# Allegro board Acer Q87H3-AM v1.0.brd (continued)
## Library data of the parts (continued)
C1-C4 C7-C9 C47-C95 C98-C105 C107-C115 C117-C123 C125-C134 C136 C138-C143 C146-C148 C151-C153 C155-C157 C160 C162-C167 C169-C211 C213 C215 C217 C219 C221 C223-C227 C229-C236 C239 C242 C245-C247 C249-C252 C254 C256 C262 C264 C281 C282 C284 C285 C287 C289-C310 C326 C329 C330 C333 C334 C337-C339 C342-C362 C364-C369 C371 C373-C379 C383-C385 C387 C388 C391-C396 C398-C406 C408-C415 C418-C420 C422 C423 C426 C428 C429 C431-C441 C444-C446 C448-C450 C452 C453 C455-C458 C460 C461 C463-C483 C486-C494 C496-C504 C506 C509 C510 C522-C526 C528 C531-C538 C541 C544 C550 C553 C554 C557-C559 C563 C571 C574 C576 C580 C583 C584 C591 C592 C597 C598 C602 C606 C607 C613 C624 C625 C652-C654 C659 C660 C663 C664 C666 C668 C670 C675 C677-C681 C683-C686 C689-C691 C696-C704 C706-C711 C722-C728 C736 C737 C740 C741 C745-C749 C751-C757 C760 C762 C763 C765-C767 C772-C775 C787-C793 C797 C800-C804 C807-C810 C815-C821 C823 C824 C827-C836 C839-C842 C844-C846 C848-C851 C854 C856-C858 SC1-SC12 SC15-SC20 SC22 SC25 SC27 SC30 SC31 SC34-SC41 SC43-SC46 SC48-SC52 = C0402_1
C6 C116 C144 C145 C149 C150 C154 C158 C168 C228 C237 C238 C240 C248 C253 C257-C261 C263 C268-C271 C273 C279 C280 C283 C286 C325 C328 C332 C336 C341 C380 C381 C386 C389 C390 C417 C442 C484 C495 C513 C517 C540 C548 C549 C551 C552 C564 C573 C578 C579 C590 C594 C600 C604 C605 C608 C610 C611 C676 C682 C705 C729-C731 C735 C738 C739 C742 C750 C761 C764 C768 C771 C776-C779 C781-C784 C794 C795 C825 C826 C838 C855 SC21 SC23 SC24 SC26 SC28 SC29 SC32 SC33 = C0603_1
C10-C12 C15-C46 C135 C137 C159 C161 C241 C243 C244 C255 C278 C324 C327 C331 C335 C340 C370 C372 C382 C397 C407 C425 C427 C443 C447 C451 C459 C462 C505 C507 C508 C511 C512 C514-C516 C518-C521 C527 C542 C543 C545-C547 C555 C556 C572 C575 C577 C581 C582 C585-C589 C593 C595 C596 C599 C601 C603 C609 C612 C669 C671-C674 C732-C734 C743 C744 C758 C759 C769 C770 C780 C785 C786 C796 C798 C799 C805 C806 C811-C814 C822 C843 SC14 = C0805_1
CMK1-CMK4 CMK33-CMK36 = WCM2012F2S_1
CMK9-CMK32 = CMM21_1
CMK37 = CMM21_R0402
CN1-CN8 = 8P4C
CODEC = LQFP48
COM1 = D-SUB_9P-KORTAK_1
COM2 = J5X2_COM
CPU1 = LGA1150_HSW_SKT-INTEL_1
CPU_FAN SYS_FAN = FAN4X1
D1 D8 D18 D20 D21 D23 SD1 = BAT54_132_2
D2 D3 D16 D17 = FPC_4P10_R_1
D5-D7 D11 = 1N4148
D9 D34 D40 = BAV99_132_2
D14 D15 D29-D32 = SOD_123_2
D19 D35-D39 = SOD_523
D22 = SOT23_RAC_Z_2
D24 D25 D27 D28 SD2 = SOT23_3L
DIMM1-DIMM4 = DDR3_240P_2
DP1 DP2 = CONN_DISPLAYPORT_19P_1
DVI-D = DVI_29P_MB_2
EC1 EC3 = EC3D5_8_H11MM_1P
EC2 EC4 EC6 EC46-EC48 = EC3D5_8_H11D5MM_1P
EC5 EC7-EC19 EC25 EC28-EC30 EC45 EC60 = EC2D5_6D3_H11MM
EC20-EC24 EC27 EC42 EC49-EC55 EC57 EC59 = EC2D5_6D3_H8MM
EC56 EC58 EC61 = EC3D5_8_H12MM_1P
F1 = FUSE_SMD_1
F5 = F1812
F_AUDIO = J5X2_AUDIO_1
F_PANEL = J7X2_PANEL_10P
F_USB1 F_USB2 = J5X2_USB_1394
F_USB3 = J5X1_CR
FB1-FB10 FB13-FB17 PFB1 PFB4-PFB8 PFB10 PFB11 R366 SFB1 SFB2 = FB0603_1
H1-H8 = HOLE8_5
ILAN = QFN48_PT04_3X3
INT_SPK = J4X2_4P
L1 = CHOKE_4R7K_PT3D35MM_SMD
L2 = CHOKE_2R2N_SMD_2P
L3 L7 L12 = CHOKE_9D5X11_PT7MM_H_2
L4 = CHOKE_1R0M-R_1
L5 PFB2 PFB9 PFB12 PFB13 = FB0805_1
L6 = CHOKE_4R7_PT2D65MM_SMD
L8-L11 = CHOKE-R36M_PT6D6X4D2MM_R
L13 L14 = CHOKE_2R0M_PT8X6D8MM
LPT = J13X2_LPT_1
ME_TEST = J3X2
MN1 MN2 QN1 QN6-QN13 QN20-QN23 QN30 QN34 QN36 QN38 QN44 QN47 QN55 QN56 QN58 QN68 QN69 QN71-QN76 QN82 QP9 QSW1-QSW4 = SOT23_GDS_2
P1-P12 R623 R631 R937 R941 = SHORT2-NMNP
PCH1 = BGA708_LYNX-INTEL
PCI = PCI_120P-AB
PCIE1X = PCIE_X1_36P_2
PCIE16X_1 PCIE16X_2 = PCIE_X16_164P_4
PSKM = KB_MS
Q1-Q6 = SOT363_6P
Q7 ROM1 U22 U31 U32 = SOP8_W150_PT50
QCH1-QCH4 QCL1-QCL8 QD3H1 QD3L1 QD3L2 QD5H1 QD5H2 QD5L1 QD5L2 QMH1 QML1 QML2 = Q_TDSON8-GDS-4
QN2-QN5 QN24-QN29 QN31-QN33 QN35 QN37 QN39-QN43 QN45 QN46 QN48 QN49 QN51 QN53 QN54 QN57 QN59-QN67 QN77-QN81 QN83 QN84 QP3-QP8 SQP1 = SOT23_BCE_2
QN50 QN52 = TO252_GDS
QP2 = TO251_BCE_PT90_1
R1 R4-R13 R15-R53 R56-R68 R71-R73 R75-R79 R81-R83 R85-R89 R95 R96 R98 R103-R127 R129-R133 R136-R161 R163-R229 R231-R248 R250-R256 R258 R259 R261-R265 R267-R271 R275 R277-R314 R316-R326 R329-R345 R349-R360 R367-R374 R376-R390 R395-R398 R400 R402 R403 R405 R408-R438 R440 R442-R449 R451-R454 R456-R461 R468 R471-R477 R479-R505 R507 R509-R511 R513-R515 R517-R520 R523-R526 R528-R531 R551 R552 R554 R555 R558 R561 R562 R566 R568 R570 R571 R574 R576-R580 R582-R586 R588-R591 R593 R595 R596 R598 R600-R602 R604 R606-R609 R611-R622 R624-R630 R633 R636-R638 R641-R654 R657 R694 R695 R737-R741 R761-R773 R777 R778 R783 R784 R786 R787 R789-R791 R793-R805 R808 R810 R814-R816 R818-R821 R823 R824 R826-R828 R830-R833 R835 R837-R840 R843 R845-R859 R861-R868 R871-R881 R885-R887 R889-R892 R894-R906 R909 R911 R912 R914-R919 R921 R923 R924 R927-R936 R938 R939 R942-R945 R949-R978 R980-R991 R994-R1001 RT1-RT3 SR2 SR3 SR5-SR14 SR16-SR24 SR30 SR32-SR34 SR36-SR38 SR40 SR45 SR46 SR48 SR49 SR51 SR52 SR54-SR59 = R0402_1
R80 R84 R128 R266 R375 R441 R450 R516 R564 R565 R567 R569 R572 R573 R597 R599 R610 R634 R635 R639 R640 R813 R822 R829 R836 R842 R844 R860 R869 R870 R883 R884 R888 R893 R908 R910 R913 R922 R925 R926 SR53 = R0805_1
R162 R249 R257 R260 R391-R394 R401 R404 R406 R407 R462-R467 R563 R592 R603 R632 R760 R809 R811 R812 R817 R825 R834 R841 R882 R907 R920 R1002 SR1 SR43 SR44 SR50 = R0603_1
R276 R347 R365 R469 R470 = R0603-SHORT_1
R455 = R0805-SHORT-NMNP
R508 R512 SR15 = R0603-SHORT_1-NMNP
R575 = R2512_1
RJ1-RJ12 RJ17 = RJ3_0402
RLAN = QFN64_RTL8111DP_1
RN1 RN2 RN7 RN8 RN19-RN25 RN38-RN40 RN43 RN44 = 8P4R
RN9-RN15 RN26-RN35 RN45 RN46 = 8P4R-0402
ROM2 SPIROM1 SPIROM2 = SOP8_W210_PT50
SATA1-SATA5 = SATA3_7P-HI-TOP
SATA_PWR1 SATA_PWR2 = CON6X1_2D5MM-PINREX
SJ1 = 2X30_XDP_CONN-NMNP
SPI_DEBUG = J6X2_PT1D27MM_SMD_2P
STP1-STP19 TP12 TP14 TP15 TP21 TP23 TP_VGA = TP30_SMD
SU1 SU2 U3 U6 U7 U9 U14 U15 U17 U18 U20 U24 U26 U28 = SOT23_6P_2
THER_HD = J3X2_SPDIF
TPM = J10X2_TPM_4P-ACER
U1 U2 U4 U5 U8 U10 = SOT1059_10P_1
U11 = LQFP128_PT04
U12 U13 U16 U25 = SOT23_8P_1
U19 U29 = PSOP8_W150_PT50_PAD-UP7719B_1
U21 = QFP128
U23 = TSSOP28_W170_PT065
U30 = SOP8_W150_PT50-104X120
U33 = DFN10_RT8106A_1
U34 = PSOP8_W150_PT50_PAD-UP6281
U35 U36 = SOT23_5P_1
U39 = QFN40_PT04_E2201
U40 = DFN8_PT05_ISL6208_1
U41 = QFN28_SM331L_PT04MM_1
U42 U43 = TSSOP20_W170_PT065
USB2X4 = USBX4_2
USB3_LAN = RJ45_USB3_32P
USB3F1 = CON10X2_2MM_20P_USB3_1
VGA = DVI_D-SUB_15F_1
X1-X3 = CRYSTAL
Y1 = ETXTALS-SPAD

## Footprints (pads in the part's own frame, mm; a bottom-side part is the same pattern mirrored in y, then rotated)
1N4148
  rect 1.524x1.778 smd: N(1.727,0) P(-1.727,0)
2X30_XDP_CONN-NMNP
  round 1.295 hole 1.295 unplated: (-10.071,2.667) (10.071,2.667)
  rect 0.203x2.54 smd: 1(-7.254,-3.231) 2(-7.254,2.865) 3(-6.754,-3.231) 4(-6.754,2.865) 5(-6.253,-3.231) 6(-6.253,2.865) 7(-5.753,-3.231) 8(-5.753,2.865) 9(-5.253,-3.231) 10(-5.253,2.865) 11(-4.752,-3.231) 12(-4.752,2.865) 13(-4.252,-3.231) 14(-4.252,2.865) 15(-3.752,-3.231) 16(-3.752,2.865) 17(-3.251,-3.231) 18(-3.251,2.865) 19(-2.751,-3.231) 20(-2.751,2.865) 21(-2.25,-3.231) 22(-2.25,2.865) 23(-1.75,-3.231) 24(-1.75,2.865) 25(-1.25,-3.231) 26(-1.25,2.865) 27(-0.749,-3.231) 28(-0.749,2.865) 29(-0.249,-3.231) 30(-0.249,2.865) 31(0.251,-3.231) 32(0.251,2.865) 33(0.752,-3.231) 34(0.752,2.865) 35(1.252,-3.231) 36(1.252,2.865) 37(1.753,-3.231) 38(1.753,2.865) 39(2.253,-3.231) 40(2.253,2.865) 41(2.753,-3.231) 42(2.753,2.865) 43(3.254,-3.231) 44(3.254,2.865) 45(3.754,-3.231) 46(3.754,2.865) 47(4.255,-3.231) 48(4.255,2.865) 49(4.755,-3.231) 50(4.755,2.865) 51(5.255,-3.231) 52(5.255,2.865) 53(5.756,-3.231) 54(5.756,2.865) 55(6.256,-3.231) 56(6.256,2.865) 57(6.756,-3.231) 58(6.756,2.865) 59(7.257,-3.231) 60(7.257,2.865)
8P4C
  rect 0.61x1.143 smd: 1(-1.219,-0.826) 2(-1.219,0.826) 7(1.219,-0.826) 8(1.219,0.826)
  rect 0.508x1.143 smd: 3(-0.406,-0.826) 4(-0.406,0.826) 5(0.406,-0.826) 6(0.406,0.826)
8P4R
  rect 0.61x1.143 smd: 1(-1.219,-0.826) 2(-1.219,0.826) 7(1.219,-0.826) 8(1.219,0.826)
  rect 0.508x1.143 smd: 3(-0.406,-0.826) 4(-0.406,0.826) 5(0.406,-0.826) 6(0.406,0.826)
8P4R-0402
  rect 0.432x0.864 smd: 1(-0.826,-0.638) 2(-0.826,0.638) 7(0.826,-0.638) 8(0.826,0.638)
  rect 0.279x0.864 smd: 3(-0.25,-0.638) 4(-0.25,0.638) 5(0.25,-0.638) 6(0.25,0.638)
ATX_PWR_4P_1
  rect 2.286x2.286 hole 1.422: 1(-2.1,2.8)
  round 2.286 hole 1.422: 2(2.1,2.8) 3(-2.1,-2.8) 4(2.1,-2.8)
ATX_PWR_12P-RUIYE
  rect 1.905x1.905 hole 1.397: 1(-10.5,2.75)
  round 1.905 hole 1.397: 2(-6.3,2.75) 3(-2.1,2.75) 4(2.1,2.75) 5(6.3,2.75) 6(10.5,2.75) 7(-10.5,-2.75) 8(-6.3,-2.75) 9(-2.1,-2.75) 10(2.1,-2.75) 11(6.3,-2.75) 12(10.5,-2.75)
AUDIO_JACK_13P-KORTAK
  round 2.337 hole 2.337 unplated: (0,4.85)
  round 1.372 hole 1.016: 1P(2.5,0.95) 1Q(-2.5,0.95) 2P(1.25,-4.05) 2Q(-1.25,-4.05) 3P(1.25,-9.05) 3Q(-1.25,-9.05) 5(0,0.95) 11(-5,0.95) 14(5,0.95) 21(-3.75,-4.05) 24(3.75,-4.05) 31(-3.75,-9.05) 34(3.75,-9.05)
  round 2.692 hole 2.337: G1(-6.05,4.85) G2(6.05,4.85) G3(-6.05,-6.45) G4(6.05,-6.45)
BAT54_132_2
  rect 1.016x1.016 smd: 1(-1.016,-1.143) 2(1.016,-1.143) 3(0,1.143)
BATTERY_1
  round 1.524 hole 1.016: N(0,10)
  round 1.626 hole 1.118: P(0,-10)
BAV99_132_2
  rect 1.016x1.016 smd: 1(-1.016,-1.143) 2(1.016,-1.143) 3(0,1.143)
BGA708_LYNX-INTEL
  round 1.016 smd: (-12.192,-11.684) (12.192,11.684)
  round 0.533 smd: A2(-10.171,10.299) A40(10.339,10.299) AV1(-10.799,-9.839) AV41(10.799,-9.839) AW2(-10.339,-10.299) AW40(10.339,-10.299) B1(-10.799,9.672) B41(10.799,9.839)
  round 0.406 smd: A3(-9.521,10.299) A39(9.689,10.299) AU1(-10.799,-9.081) AU41(10.799,-9.189) AV2(-10.171,-9.671) AV40(10.171,-9.671) AW3(-9.689,-10.299) AW39(9.689,-10.299) B2(-10.14,9.639) B40(10.171,9.671) C1(-10.799,9.021) C41(10.799,9.081)
  round 0.381 smd: A4(-8.732,10.299) A7(-7.653,10.314) A9(-6.383,10.314) A12(-5.113,10.314) A31(5.098,10.314) A33(6.369,10.314) A35(7.639,10.314) A38(8.965,10.299) AA6(-8.135,-0.464) AA7(-7.424,-0.464) AA8(-6.713,-0.464) AA10(-6.002,-0.464) AA11(-5.29,-0.464) AA12(-4.579,-0.464) AA14(-3.629,-0.423) AA16(-2.823,-0.423) AA17(-2.016,-0.423) AA19(-1.21,-0.423) AA20(-0.403,-0.423) AA22(0.403,-0.423) AA23(1.21,-0.423) AA25(2.016,-0.423) AA26(2.822,-0.423) AA28(3.629,-0.423) AA30(4.579,-0.464) AA31(5.29,-0.464) AA32(6.002,-0.464) AA34(6.713,-0.464) AA35(7.424,-0.464) AA36(8.135,-0.464) AB14(-3.629,-1.269) AB16(-2.823,-1.269) AB17(-2.016,-1.269) AB19(-1.21,-1.269) AB20(-0.403,-1.269) AB22(0.403,-1.269) AB23(1.21,-1.269) AB25(2.016,-1.269) AB26(2.822,-1.269) AB28(3.629,-1.269) AC6(-8.186,-1.53) AC7(-7.424,-1.53) AC8(-6.713,-1.53) AC10(-6.002,-1.53) AC11(-5.29,-1.53) AC12(-4.579,-1.53) AC30(4.579,-1.53) AC31(5.29,-1.53) AC32(6.002,-1.53) AC34(6.713,-1.53) AC35(7.424,-1.53) AC36(8.186,-1.53) AD14(-3.629,-2.115) AD16(-2.823,-2.115) AD17(-2.016,-2.115) AD19(-1.21,-2.115) AD20(-0.403,-2.115) AD22(0.403,-2.115) AD23(1.21,-2.115) AD25(2.016,-2.115) AD26(2.822,-2.115) AD28(3.629,-2.115) AE6(-8.135,-2.597) AE7(-7.424,-2.597) AE8(-6.713,-2.597) AE10(-6.002,-2.597) AE11(-5.29,-2.597) AE12(-4.64,-2.597) AE30(4.64,-2.597) AE31(5.29,-2.597) AE32(6.002,-2.597) AE34(6.713,-2.597) AE35(7.424,-2.597) AE36(8.135,-2.597) AF14(-3.629,-2.96) AF16(-2.823,-2.96) AF17(-2.016,-2.96) AF19(-1.21,-2.96) AF20(-0.403,-2.96) AF22(0.403,-2.96) AF23(1.21,-2.96) AF25(2.016,-2.96) AF26(2.822,-2.96) AF28(3.629,-2.96) AG6(-8.135,-3.804) AG7(-7.424,-3.804) AG8(-6.713,-3.804) AG10(-6.002,-3.804) AG11(-5.29,-3.804) AG12(-4.579,-3.804) AG30(4.64,-3.804) AG31(5.29,-3.804) AG32(6.002,-3.804) AG34(6.713,-3.804) AG35(7.424,-3.804) AG36(8.135,-3.804) AH14(-3.804,-4.14) AH16(-2.597,-4.14) AH18(-1.53,-4.079) AH20(-0.464,-4.079) AH22(0.464,-4.079) AH24(1.53,-4.079) AH26(2.597,-4.14) AH28(3.804,-4.14) AJ1(-10.814,-5.118) AJ14(-3.804,-4.79) AJ16(-2.597,-4.79) AJ18(-1.53,-4.79) AJ20(-0.464,-4.79) AJ22(0.464,-4.79) AJ24(1.53,-4.79) AJ26(2.597,-4.79) AJ28(3.804,-4.79) AJ31(5.164,-5.016) AK6(-7.828,-5.086) AK8(-7.117,-5.086) AK9(-6.405,-5.086) AK11(-5.086,-5.133) AK14(-3.804,-5.502) AK16(-2.597,-5.502) AK18(-1.53,-5.502) AK20(-0.464,-5.502) AK22(0.464,-5.502) AK24(1.53,-5.502) AK26(2.597,-5.502) AK28(3.804,-5.502) AK33(6.344,-5.086) AK34(7.056,-5.086) AK36(7.818,-5.086) AK41(10.814,-5.288) AL11(-5.086,-5.845) AL31(5.086,-5.906) AM1(-10.814,-6.388) AM6(-8.135,-6.179) AM7(-7.485,-6.179) AM8(-6.835,-6.179) AM9(-6.189,-6.335) AM11(-5.086,-6.556) AM14(-3.804,-6.213) AM16(-2.597,-6.213) AM18(-1.53,-6.213) AM20(-0.464,-6.213) AM22(0.464,-6.213) AM24(1.53,-6.213) AM26(2.597,-6.213) AM28(3.804,-6.213) AM31(5.086,-6.617) AM33(6.179,-6.274) AM34(6.835,-6.189) AM35(7.485,-6.189) AM36(8.135,-6.189) AM41(10.814,-6.558) AN9(-6.189,-6.985) AN14(-3.804,-6.924) AN16(-2.597,-6.924) AN18(-1.53,-6.924) AN20(-0.464,-6.924) AN22(0.464,-6.924) AN24(1.53,-6.924) AN26(2.597,-6.924) AN28(3.804,-6.924) AN33(6.179,-6.924) AP1(-10.814,-7.658) AP7(-7.332,-7.352) AP9(-6.189,-7.635) AP11(-5.086,-7.318) AP14(-3.804,-7.635) AP16(-2.597,-7.635) AP18(-1.53,-7.686) AP20(-0.464,-7.635) AP22(0.464,-7.635) AP24(1.53,-7.686) AP26(2.597,-7.635) AP28(3.804,-7.635) AP31(5.086,-7.328) AP33(6.179,-7.635) AP35(7.325,-7.347) AR41(10.814,-7.828) AT1(-10.799,-8.357) AT2(-10.148,-8.357) AT40(10.168,-8.357) AT41(10.799,-8.539) AU2(-10.15,-9.021) AU40(10.169,-9.021) AV3(-9.52,-9.671) AV5(-8.34,-9.758) AV39(9.496,-9.671) AW4(-8.965,-10.299) AW7(-7.639,-10.314) AW9(-6.369,-10.314) AW11(-5.099,-10.314) AW30(5.112,-10.314) AW33(6.382,-10.314) AW35(7.652,-10.314) AW38(8.965,-10.299) B3(-9.48,9.639) B37(8.34,9.758) B39(9.52,9.671) C2(-10.14,8.978) C40(10.15,9.021) D1(-10.799,8.371) D2(-10.129,8.327) D40(10.148,8.357) D41(10.799,8.357) E1(-10.814,7.638) F7(-7.325,7.347) F9(-6.179,7.635) F11(-5.086,7.328) F14(-3.804,7.635) F16(-2.597,7.635) F18(-1.53,7.686) F20(-0.464,7.635) F22(0.464,7.635) F24(1.53,7.686) F26(2.597,7.635) F28(3.804,7.635) F31(5.086,7.318) F33(6.189,7.635) F35(7.332,7.352) F41(10.814,7.658) G9(-6.179,6.924) G14(-3.804,6.924) G16(-2.597,6.924) G18(-1.53,6.924) G20(-0.464,6.924) G22(0.464,6.924) G24(1.53,6.924) G26(2.597,6.924) G28(3.804,6.924) G33(6.189,6.985) H1(-10.814,6.558) H6(-8.135,6.189) H7(-7.485,6.189) H8(-6.835,6.189) H9(-6.179,6.274) H11(-5.086,6.617) H14(-3.804,6.213) H16(-2.597,6.213) H18(-1.53,6.213) H20(-0.464,6.213) H22(0.464,6.213) H24(1.53,6.213) H26(2.597,6.213) H28(3.804,6.213) H31(5.086,6.556) H33(6.189,6.335) H34(6.835,6.179) H35(7.485,6.179) H36(8.135,6.179) H41(10.814,6.388) J11(-5.086,5.906) J31(5.086,5.845) K1(-10.814,5.288) K6(-7.818,5.086) K8(-7.056,5.086) K9(-6.344,5.086) K14(-3.804,5.502) K16(-2.597,5.502) K18(-1.53,5.502) K20(-0.464,5.502) K22(0.464,5.502) K24(1.53,5.502) K26(2.597,5.502) K28(3.804,5.502) K31(5.086,5.133) K33(6.405,5.086) K34(7.117,5.086) K36(7.828,5.086) L11(-5.164,5.016) L14(-3.804,4.79) L16(-2.597,4.79) L18(-1.53,4.79) L20(-0.464,4.79) L22(0.464,4.79) L24(1.53,4.79) L26(2.597,4.79) L28(3.804,4.79) L41(10.814,5.118) M14(-3.804,4.14) M16(-2.597,4.14) M18(-1.53,4.079) M20(-0.464,4.079) M22(0.464,4.079) M24(1.53,4.079) M26(2.597,4.14) M28(3.804,4.14) N6(-8.135,3.804) N7(-7.424,3.804) N8(-6.713,3.804) N10(-6.002,3.804) N11(-5.29,3.804) N12(-4.64,3.804) N30(4.579,3.804) N31(5.29,3.804) N32(6.002,3.804) N34(6.713,3.804) N35(7.424,3.804) N36(8.135,3.804) P14(-3.629,2.96) P16(-2.823,2.96) P17(-2.016,2.96) P19(-1.21,2.96) P20(-0.403,2.96) P22(0.403,2.96) P23(1.21,2.96) P25(2.016,2.96) P26(2.822,2.96) P28(3.629,2.96) R6(-8.135,2.597) R7(-7.424,2.597) R8(-6.713,2.597) R10(-6.002,2.597) R11(-5.29,2.597) R12(-4.64,2.597) R30(4.64,2.597) R31(5.29,2.597) R32(6.002,2.597) R34(6.713,2.597) R35(7.424,2.597) R36(8.135,2.597) T14(-3.629,2.115) T16(-2.823,2.115) T17(-2.016,2.115) T19(-1.21,2.115) T20(-0.403,2.115) T22(0.403,2.115) T23(1.21,2.115) T25(2.016,2.115) T26(2.822,2.115) T28(3.629,2.115) U6(-8.186,1.53) U7(-7.424,1.53) U8(-6.713,1.53) U10(-6.002,1.53) U11(-5.29,1.53) U12(-4.579,1.53) U30(4.579,1.53) U31(5.29,1.53) U32(6.002,1.53) U34(6.713,1.53) U35(7.424,1.53) U36(8.186,1.53) V14(-3.629,1.269) V16(-2.823,1.269) V17(-2.016,1.269) V19(-1.21,1.269) V20(-0.403,1.269) V22(0.403,1.269) V23(1.21,1.269) V25(2.016,1.269) V26(2.822,1.269) V28(3.629,1.269) W6(-8.135,0.464) W7(-7.424,0.464) W8(-6.713,0.464) W10(-6.002,0.464) W11(-5.29,0.464) W12(-4.579,0.464) W14(-3.629,0.423) W16(-2.823,0.423) W17(-2.016,0.423) W19(-1.21,0.423) W20(-0.403,0.423) W22(0.403,0.423) W23(1.21,0.423) W25(2.016,0.423) W26(2.822,0.423) W28(3.629,0.423) W30(4.579,0.464) W31(5.29,0.464) W32(6.002,0.464) W34(6.713,0.464) W35(7.424,0.464) W36(8.135,0.464)
  oval 0.254x0.343 smd: A14(-3.703,10.314) A16(-2.534,10.314) A19(-1.176,10.314) A21(-0.007,10.314) A24(1.352,10.314) A26(2.52,10.314) A28(3.879,10.314) AB4(-8.818,-1.181) AC38(8.818,-1.349) AG4(-8.818,-3.71) AG38(8.818,-3.879) AL5(-8.779,-5.631) AM4(-8.818,-6.28) AM38(8.818,-6.498) AW14(-3.88,-10.314) AW16(-2.521,-10.314) AW18(-1.352,-10.314) AW21(0.007,-10.314) AW23(1.175,-10.314) AW26(2.534,-10.314) AW28(3.702,-10.314) H4(-8.818,6.498) H38(8.818,6.28) J37(8.779,5.631) N4(-8.818,3.879) N38(8.818,3.71) U4(-8.818,1.349) V38(8.818,1.181)
  round 0.305 smd: AA2(-10.306,-0.432) AA3(-9.479,-0.486) AA5(-8.787,-0.491) AA37(8.787,-0.677) AA39(9.479,-0.677) AA40(10.289,-0.677) AB2(-9.916,-1.181) AC2(-10.289,-1.853) AC3(-9.479,-1.853) AC5(-8.779,-1.853) AC40(9.916,-1.349) AD37(8.779,-2.044) AD39(9.479,-2.044) AD40(10.306,-2.098) AE2(-9.87,-2.479) AE4(-9.128,-2.466) AE38(9.128,-2.593) AE40(9.87,-2.581) AF2(-10.306,-2.962) AF3(-9.479,-3.015) AF5(-8.779,-3.015) AF37(8.779,-3.207) AF39(9.479,-3.207) AF40(10.289,-3.207) AG2(-9.916,-3.71) AG40(9.916,-3.823) AH2(-10.212,-4.383) AH3(-9.479,-4.383) AH5(-8.779,-4.383) AJ2(-9.87,-5.009) AJ4(-9.128,-4.995) AJ5(-8.478,-4.968) AJ37(8.779,-4.574) AJ39(9.479,-4.574) AJ40(10.306,-4.58) AK37(8.478,-5.182) AK38(9.128,-5.212) AK40(9.87,-5.208) AL2(-10.306,-5.579) AL3(-9.479,-5.632) AL37(8.779,-5.826) AL39(9.479,-5.826) AL40(10.289,-5.826) AM2(-9.916,-6.327) AM40(9.916,-6.485) AN2(-10.205,-7.009) AN3(-9.479,-6.999) AN4(-8.83,-6.931) AN37(8.779,-7.193) AN39(9.479,-7.193) AN40(10.289,-7.255) AP2(-9.87,-7.626) AP4(-9.132,-7.567) AP5(-8.482,-7.567) AR4(-8.859,-8.157) AR7(-7.684,-7.978) AR11(-5.154,-7.978) AR30(4.968,-7.978) AR35(7.498,-7.978) AR37(8.478,-7.78) AR38(9.128,-7.742) AR39(9.853,-7.738) AT5(-8.283,-8.462) AT7(-7.654,-8.628) AT8(-7.104,-8.279) AT10(-5.737,-8.279) AT11(-5.124,-8.628) AT12(-4.575,-8.279) AT15(-3.208,-8.279) AT16(-2.594,-8.628) AT17(-2.045,-8.279) AT20(-0.678,-8.287) AT21(-0.064,-8.628) AT22(0.49,-8.287) AT24(1.852,-8.279) AT26(2.466,-8.628) AT27(3.015,-8.279) AT29(4.382,-8.279) AT30(4.994,-8.628) AT31(5.545,-8.279) AT34(6.912,-8.279) AT35(7.524,-8.628) AT36(8.115,-8.352) AT38(8.843,-8.357) AU3(-9.496,-9.021) AU5(-8.246,-9.115) AU8(-7.104,-8.979) AU10(-5.737,-8.979) AU12(-4.575,-8.979) AU15(-3.208,-8.979) AU17(-2.045,-8.979) AU20(-0.678,-8.979) AU22(0.485,-8.979) AU24(1.852,-8.979) AU27(3.015,-8.979) AU29(4.382,-8.979) AU31(5.545,-8.979) AU34(6.912,-8.979) AU36(8.115,-9.005) AU39(9.496,-9.021) AV4(-8.908,-9.395) AV7(-7.641,-9.371) AV8(-7.158,-9.806) AV9(-6.409,-9.416) AV10(-5.737,-9.725) AV11(-5.111,-9.371) AV12(-4.628,-9.806) AV14(-3.88,-9.416) AV15(-3.208,-9.789) AV16(-2.581,-9.371) AV17(-2.098,-9.806) AV18(-1.35,-9.416) AV20(-0.678,-9.789) AV21(-0.051,-9.371) AV22(0.432,-9.806) AV23(1.18,-9.416) AV24(1.852,-9.789) AV26(2.479,-9.371) AV27(2.962,-9.806) AV28(3.71,-9.416) AV29(4.382,-9.789) AV30(5.008,-9.351) AV31(5.545,-9.786) AV33(6.303,-9.416) AV34(6.912,-9.789) AV35(7.538,-9.371) AV36(8.113,-9.756) AV38(8.843,-9.652) B4(-8.849,9.457) B6(-8.187,9.781) B7(-7.539,9.371) B8(-6.912,9.789) B9(-6.304,9.416) B11(-5.545,9.786) B12(-5.009,9.351) B13(-4.383,9.789) B14(-3.71,9.416) B15(-2.962,9.806) B16(-2.479,9.371) B18(-1.853,9.789) B19(-1.181,9.416) B20(-0.432,9.806) B21(0.051,9.371) B22(0.677,9.789) B24(1.349,9.416) B25(2.098,9.806) B26(2.581,9.371) B27(3.207,9.789) B28(3.879,9.416) B30(4.627,9.806) B31(5.11,9.371) B32(5.737,9.725) B33(6.409,9.416) B34(7.158,9.806) B35(7.641,9.371) B38(8.908,9.395) C3(-9.48,8.978) C6(-8.187,9.005) C8(-6.912,8.979) C11(-5.545,8.979) C13(-4.383,8.979) C15(-3.015,8.979) C18(-1.853,8.979) C20(-0.486,8.979) C22(0.677,8.979) C25(2.044,8.979) C27(3.207,8.979) C30(4.574,8.979) C32(5.737,8.979) C34(7.104,8.979) C37(8.246,9.115) C39(9.496,9.021) D4(-8.849,8.339) D6(-8.187,8.354) D7(-7.498,8.628) D8(-6.912,8.279) D11(-5.545,8.279) D12(-4.995,8.628) D13(-4.383,8.279) D15(-3.015,8.279) D16(-2.466,8.628) D18(-1.853,8.279) D20(-0.491,8.287) D21(0.064,8.628) D22(0.677,8.287) D25(2.044,8.279) D26(2.593,8.628) D27(3.207,8.279) D30(4.574,8.279) D31(5.123,8.628) D32(5.737,8.279) D34(7.104,8.279) D35(7.654,8.628) D37(8.283,8.462) E3(-9.815,7.752) E4(-9.129,7.752) E5(-8.452,7.752) E7(-7.498,7.978) E12(-4.968,7.978) E31(5.154,7.978) E35(7.684,7.978) E38(8.859,8.157) F37(8.482,7.567) F38(9.132,7.567) F40(9.87,7.626) G2(-10.289,7.255) G3(-9.479,7.19) G5(-8.779,7.19) G38(8.83,6.931) G39(9.479,6.999) G40(10.205,7.009) H2(-9.916,6.485) H40(9.916,6.327) J2(-10.289,5.826) J3(-9.479,5.826) J5(-8.779,5.826) J39(9.479,5.632) J40(10.306,5.579) K2(-9.87,5.208) K4(-9.128,5.212) K5(-8.478,5.182) L2(-10.306,4.58) L3(-9.479,4.574) L5(-8.779,4.574) L37(8.478,4.968) L38(9.128,4.995) L40(9.87,5.009) M37(8.779,4.383) M39(9.479,4.383) M40(10.212,4.383) N2(-9.916,3.823) N40(9.916,3.71) P2(-10.289,3.207) P3(-9.479,3.207) P5(-8.779,3.207) P37(8.779,3.015) P39(9.479,3.015) P40(10.306,2.962) R2(-9.87,2.581) R4(-9.128,2.593) R38(9.128,2.466) R40(9.87,2.479) T2(-10.306,2.098) T3(-9.479,2.044) T5(-8.779,2.044) U2(-9.916,1.349) U37(8.779,1.853) U39(9.479,1.853) U40(10.289,1.853) V40(9.916,1.181) W2(-10.289,0.677) W3(-9.479,0.677) W5(-8.787,0.677) W37(8.787,0.491) W39(9.479,0.486) W40(10.306,0.432) Y2(-9.87,0.051) Y4(-9.128,0.064) Y38(9.128,-0.064) Y40(9.87,-0.051)
  oval 0.343x0.254 smd: AB1(-10.814,-1.181) AC41(10.814,-1.349) AE1(-10.814,-2.54) AE41(10.814,-2.52) AG1(-10.814,-3.708) AG41(10.814,-3.879) AT9(-6.409,-8.319) AT14(-3.88,-8.319) AT18(-1.35,-8.319) AT23(1.18,-8.319) AT28(3.71,-8.319) AT33(6.24,-8.319) D9(-6.24,8.319) D14(-3.71,8.319) D19(-1.181,8.319) D24(1.349,8.319) D28(3.879,8.319) D33(6.409,8.319) N1(-10.814,3.879) N41(10.814,3.708) R1(-10.814,2.52) R41(10.814,2.54) U1(-10.814,1.349) V41(10.814,1.181) Y1(-10.814,-0.01) Y41(10.814,0.01)
BUZZER_1
  round 1.372 hole 0.914: N(3.251,0) P(-3.251,0)
C0402_1
  rect 0.572x0.508 smd: 1(-0.476,0) 2(0.476,0)
C0603_1
  rect 0.889x0.762 smd: 1(-0.699,0) 2(0.699,0)
C0805_1
  rect 1.016x1.397 smd: 1(-0.889,0) 2(0.889,0)
CHOKE-R36M_PT6D6X4D2MM_R
  round 2.388 hole 1.93: 1(3.3,2.1)
  oval 2.845x2.388 hole 2.388x1.93 rot 45: 2(-3.3,-2.1)
CHOKE_1R0M-R_1
  round 2.184 hole 1.727: 1(-3.45,2.35)
  oval 2.489x2.184 hole 2.032x1.727 rot 135: 2(3.45,-2.35)
CHOKE_2R0M_PT8X6D8MM
  round 2.032 hole 1.626: 1(-4,3.4)
  oval 2.54x2.083 hole 2.083x1.626 rot 135: 2(4,-3.4)
CHOKE_2R2N_SMD_2P
  rect 1.75x4.5 smd: 1(-1.625,0) 2(1.625,0)
CHOKE_4R7_PT2D65MM_SMD
  rect 1.676x4.597 smd: 1(-1.325,0) 2(1.325,0)
CHOKE_4R7K_PT3D35MM_SMD
  rect 2.159x4.318 smd: 1(-1.675,0) 2(1.675,0)
CHOKE_9D5X11_PT7MM_H_2
  oval 1.981x2.438 hole 1.524x1.981: 1(-3.5,0)
  oval 2.438x1.981 hole 1.981x1.524: 2(3.5,0)
CMM21_1
  rect 0.45x0.9 smd: 1(-0.425,0.85) 2(-0.425,-0.85) 3(0.425,-0.85) 4(0.425,0.85)
CMM21_R0402
  custom 0.127x0.127 smd: 1(-0.504,0.745) 2(-0.504,-0.745) 3(0.504,-0.745) 4(0.504,0.745)
CON6X1_2D5MM-PINREX
  rect 1.372x1.372 hole 1.016: 1(-6.25,-0.525)
  round 1.372 hole 1.016: 2(-3.75,-0.525) 3(-1.25,-0.525) 4(1.25,-0.525) 5(3.75,-0.525) 6(6.25,-0.525)
CON10X2_2MM_20P_USB3_1
  round 1.168 hole 0.813: 1(-9,1) 2(-7,1) 3(-5,1) 4(-3,1) 5(-1,1) 6(1,1) 7(3,1) 8(5,1) 9(7,1) 10(9,1) 11(9,-1) 12(7,-1) 13(5,-1) 14(3,-1) 15(1,-1) 16(-1,-1) 17(-3,-1) 18(-5,-1) 19(-7,-1)
CONN_DISPLAYPORT_19P_1
  round 0.711 hole 0.406: 1(6.36,0.4) 2(5,-0.6) 3(5.36,0.4) 4(4,-0.6) 5(4.36,0.4) 6(3,-0.6) 7(2.51,0.4) 8(2,-0.6) 9(1.51,0.4) 10(1,-0.6) 11(-0.35,0.4) 12(0,-0.6) 13(-1.35,0.4) 14(-1,-0.6) 15(-2.35,0.4) 16(-2,-0.6) 17(-3.35,0.4) 18(-3,-0.6) 19(-4.35,0.4) 20(-4,-0.6)
  oval 1.321x2.845 hole 0.711x2.235: G1(-8.25,0) G2(8.25,0)
  oval 1.321x2.337 hole 0.711x1.727: G3(-8.25,-6.48) G4(8.25,-6.48)
CRYSTAL
  round 1.067 hole 0.711: 1(-2.54,0) 2(2.54,0)
  round 0.813 hole 0.508: 3(0,0)
D-SUB_9P-KORTAK_1
  rect 1.524x1.524 hole 1.118: 1(5.54,-1.42)
  round 1.524 hole 1.118: 2(2.77,-1.42) 3(0,-1.42) 4(-2.77,-1.42) 5(-5.54,-1.42) 6(4.155,1.42) 7(1.385,1.42) 8(-1.385,1.42) 9(-4.155,1.42)
  round 3.607 hole 3.251: 10(12.42,0) 11(-12.57,0) 12(0,10.36)
DDR3_240P_2
  round 2.464 hole 2.464 unplated: (0.95,7.5) (0.95,-130.5)
  oval 2.438x1.829 hole 2.438x1.829 unplated: (0.95,-49.5)
  rect 1.016x1.016 hole 0.711: 1(0,0)
  round 1.016 hole 0.711: 2(-1.9,-1) 3(0,-2) 4(-1.9,-3) 5(0,-4) 6(-1.9,-5) 7(0,-6) 8(-1.9,-7) 9(0,-8) 10(-1.9,-9) 11(0,-10) 12(-1.9,-11) 13(0,-12) 14(-1.9,-13) 15(0,-14) 16(-1.9,-15) 17(0,-16) 18(-1.9,-17) 19(0,-18) 20(-1.9,-19) 21(0,-20) 22(-1.9,-21) 23(0,-22) 24(-1.9,-23) 25(0,-24) 26(-1.9,-25) 27(0,-26) 28(-1.9,-27) 29(0,-28) 30(-1.9,-29) 31(0,-30) 32(-1.9,-31) 33(0,-32) 34(-1.9,-33) 35(0,-34) 36(-1.9,-35) 37(0,-36) 38(-1.9,-37) 39(0,-38) 40(-1.9,-39) 41(0,-40) 42(-1.9,-41) 43(0,-42) 44(-1.9,-43) 45(0,-44) 46(-1.9,-45) 47(0,-46) 48(-1.9,-47) 49(0,-52) 50(-1.9,-53) 51(0,-54) 52(-1.9,-55) 53(0,-56) 54(-1.9,-57) 55(0,-58) 56(-1.9,-59) 57(0,-60) 58(-1.9,-61) 59(0,-62) 60(-1.9,-63) 61(0,-64) 62(-1.9,-65) 63(0,-66) 64(-1.9,-67) 65(0,-68) 66(-1.9,-69) 67(0,-70) 68(-1.9,-71) 69(0,-72) 70(-1.9,-73) 71(0,-74) 72(-1.9,-75) 73(0,-76) 74(-1.9,-77) 75(0,-78) 76(-1.9,-79) 77(0,-80) 78(-1.9,-81) 79(0,-82) 80(-1.9,-83) 81(0,-84) 82(-1.9,-85) 83(0,-86) 84(-1.9,-87) 85(0,-88) 86(-1.9,-89) 87(0,-90) 88(-1.9,-91) 89(0,-92) 90(-1.9,-93) 91(0,-94) 92(-1.9,-95) 93(0,-96) 94(-1.9,-97) 95(0,-98) 96(-1.9,-99) 97(0,-100) 98(-1.9,-101) 99(0,-102) 100(-1.9,-103) 101(0,-104) 102(-1.9,-105) 103(0,-106) 104(-1.9,-107) 105(0,-108) 106(-1.9,-109) 107(0,-110) 108(-1.9,-111) 109(0,-112) 110(-1.9,-113) 111(0,-114) 112(-1.9,-115) 113(0,-116) 114(-1.9,-117) 115(0,-118) 116(-1.9,-119) 117(0,-120) 118(-1.9,-121) 119(0,-122) 120(-1.9,-123) 121(3.8,0) 122(1.9,-1) 123(3.8,-2) 124(1.9,-3) 125(3.8,-4) 126(1.9,-5) 127(3.8,-6) 128(1.9,-7) 129(3.8,-8) 130(1.9,-9) 131(3.8,-10) 132(1.9,-11) 133(3.8,-12) 134(1.9,-13) 135(3.8,-14) 136(1.9,-15) 137(3.8,-16) 138(1.9,-17) 139(3.8,-18) 140(1.9,-19) 141(3.8,-20) 142(1.9,-21) 143(3.8,-22) 144(1.9,-23) 145(3.8,-24) 146(1.9,-25) 147(3.8,-26) 148(1.9,-27) 149(3.8,-28) 150(1.9,-29) 151(3.8,-30) 152(1.9,-31) 153(3.8,-32) 154(1.9,-33) 155(3.8,-34) 156(1.9,-35) 157(3.8,-36) 158(1.9,-37) 159(3.8,-38) 160(1.9,-39) 161(3.8,-40) 162(1.9,-41) 163(3.8,-42) 164(1.9,-43) 165(3.8,-44) 166(1.9,-45) 167(3.8,-46) 168(1.9,-47) 169(3.8,-52) 170(1.9,-53) 171(3.8,-54) 172(1.9,-55) 173(3.8,-56) 174(1.9,-57) 175(3.8,-58) 176(1.9,-59) 177(3.8,-60) 178(1.9,-61) 179(3.8,-62) 180(1.9,-63) 181(3.8,-64) 182(1.9,-65) 183(3.8,-66) 184(1.9,-67) 185(3.8,-68) 186(1.9,-69) 187(3.8,-70) 188(1.9,-71) 189(3.8,-72) 190(1.9,-73) 191(3.8,-74) 192(1.9,-75) 193(3.8,-76) 194(1.9,-77) 195(3.8,-78) 196(1.9,-79) 197(3.8,-80) 198(1.9,-81) 199(3.8,-82) 200(1.9,-83) 201(3.8,-84) 202(1.9,-85) 203(3.8,-86) 204(1.9,-87) 205(3.8,-88) 206(1.9,-89) 207(3.8,-90) 208(1.9,-91) 209(3.8,-92) 210(1.9,-93) 211(3.8,-94) 212(1.9,-95) 213(3.8,-96) 214(1.9,-97) 215(3.8,-98) 216(1.9,-99) 217(3.8,-100) 218(1.9,-101) 219(3.8,-102) 220(1.9,-103) 221(3.8,-104) 222(1.9,-105) 223(3.8,-106) 224(1.9,-107) 225(3.8,-108) 226(1.9,-109) 227(3.8,-110) 228(1.9,-111) 229(3.8,-112) 230(1.9,-113) 231(3.8,-114) 232(1.9,-115) 233(3.8,-116) 234(1.9,-117) 235(3.8,-118) 236(1.9,-119) 237(3.8,-120) 238(1.9,-121) 239(3.8,-122) 240(1.9,-123)
DFN8_PT05_ISL6208_1
  oval 0.279x0.559 smd: 1(-0.75,-0.95) 2(-0.25,-0.95) 3(0.25,-0.95) 4(0.75,-0.95) 5(0.75,0.95) 6(0.25,0.95) 7(-0.25,0.95) 8(-0.75,0.95)
  rect 1.55x0.9 smd: 9(0,0)
DFN10_RT8106A_1
  rect 0.305x0.711 smd: 1(-1,-1.371) 2(-0.5,-1.371) 3(0,-1.371) 4(0.5,-1.371) 5(1,-1.371) 6(1,1.371) 7(0.5,1.371) 8(0,1.371) 9(-0.5,1.371) 10(-1,1.371)
  rect 2.489x1.372 smd: 11(0,0)
DVI_29P_MB_2
  round 1.27 hole 0.864: 1(9.525,-6.885) 2(7.62,-6.885) 3(5.715,-6.885) 4(3.81,-6.885) 5(1.905,-6.885) 6(0,-6.885) 7(-1.905,-6.885) 8(-3.81,-6.885) 9(9.525,-4.98) 10(7.62,-4.98) 11(5.715,-4.98) 12(3.81,-4.98) 13(1.905,-4.98) 14(0,-4.98) 15(-1.905,-4.98) 16(-3.81,-4.98) 17(9.525,-3.075) 18(7.62,-3.075) 19(5.715,-3.075) 20(3.81,-3.075) 21(1.905,-3.075) 22(0,-3.075) 23(-1.905,-3.075) 24(-3.81,-3.075) C1(-6.985,-6.265) C2(-9.525,-6.265) C3(-6.985,-3.725) C4(-9.525,-3.725) C5(-8.255,-7.535) C6(-8.255,-2.455)
  round 3.658 hole 3.251: M1(-15.9,-1.55) M2(15.9,-1.55)
DVI_D-SUB_15F_1
  round 1.524 smd: (-7.12,12.37) (-7.12,7.29) (-5.975,9.83) (6.62,12.37) (7.765,9.83) (8.91,12.37)
  round 1.524 hole 1.118: 1(4.33,12.37) 2(2.04,12.37) 3(-0.25,12.37) 4(-2.54,12.37) 5(-4.83,12.37) 6(5.475,9.83) 7(3.185,9.83) 8(0.895,9.83) 9(-1.395,9.83) 10(-3.685,9.83) 11(4.33,7.29) 12(2.04,7.29) 13(-0.25,7.29) 14(-2.54,7.29) 15(-4.83,7.29)
  round 3.607 hole 3.251: G1(-12.495,8.71) G2(12.495,8.71)
EC2D5_6D3_H8MM
  round 1.372 hole 1.016: 1(-1.25,0) 2(1.25,0)
EC2D5_6D3_H11MM
  round 1.372 hole 1.016: 1(-1.25,0) 2(1.25,0)
EC3D5_8_H11D5MM_1P
  round 1.676 hole 1.219: 1(-1.75,0)
  round 1.372 hole 1.016: 2(1.75,0)
EC3D5_8_H11MM_1P
  round 1.676 hole 1.219: 1(-1.75,0)
  round 1.372 hole 1.016: 2(1.75,0)
EC3D5_8_H12MM_1P
  round 1.676 hole 1.219: 1(-1.75,0)
  round 1.372 hole 1.016: 2(1.75,0)
ETXTALS-SPAD
  round 1.016 hole 0.66: 1(-6.35,-1.27) 2(-6.35,1.27)
  round 1.27 hole 0.813: 3(0,-2.54) 4(0,2.54)
F1812
  rect 1.676x2.896 smd: 1(-2.39,0) 2(2.39,0)
FAN4X1
  rect 1.448x1.448 hole 1.092: 1(3.81,0.115)
  round 1.448 hole 1.092: 2(1.27,0.115) 3(-1.27,0.115) 4(-3.81,0.115)
FB0603_1
  rect 0.889x0.762 smd: 1(-0.699,0) 2(0.699,0)
FB0805_1
  rect 1.143x1.397 smd: 1(-0.953,0) 2(0.953,0)
FPC_4P10_R_1
  rect 0.2x0.675 smd: 1(-1,-0.437) 2(-0.5,-0.437) 4(0.5,-0.437) 5(1,-0.437) 6(1,0.437) 7(0.5,0.437) 9(-0.5,0.437) 10(-1,0.437)
  rect 0.4x1.55 smd: 8(0,0)
FUSE_SMD_1
  rect 1.905x3.404 smd: 1(-2.223,0) 2(2.223,0)
HOLE8_5
  round 4.064 hole 4.064 unplated: (0,0)
  round 0.66 hole 0.356: 1(0,3.992) 2(-2.823,2.823) 3(-3.992,0) 4(-2.823,-2.823) 5(0,-3.992) 6(2.823,-2.823) 7(3.992,0) 8(2.823,2.823)
J2X1
  rect 1.372x1.372 hole 1.016: 1(-1.27,0)
  round 1.372 hole 1.016: 2(1.27,0)
J3X1
  rect 1.372x1.372 hole 1.016: 1(-2.54,0)
  round 1.372 hole 1.016: 2(0,0) 3(2.54,0)
J3X2
  rect 1.372x1.372 hole 1.016: 1(-2.54,-1.27)
  round 1.372 hole 1.016: 2(-2.54,1.27) 3(0,-1.27) 4(0,1.27) 5(2.54,-1.27) 6(2.54,1.27)
J3X2_SPDIF
  rect 1.372x1.372 hole 1.016: 1(-2.54,-1.27)
  round 1.372 hole 1.016: 2(-2.54,1.27) 3(0,-1.27) 5(2.54,-1.27) 6(2.54,1.27)
J4X2_4P
  rect 1.372x1.372 hole 1.016: 1(-3.81,-1.27)
  round 1.372 hole 1.016: 2(-3.81,1.27) 3(-1.27,-1.27) 5(1.27,-1.27) 6(1.27,1.27) 7(3.81,-1.27) 8(3.81,1.27)
J5X1_CR
  rect 1.372x1.372 hole 1.016: 1(-5.08,0)
  round 1.372 hole 1.016: 2(-2.54,0) 3(0,0) 4(2.54,0)
J5X2_AUDIO_1
  rect 1.372x1.372 hole 1.016: 1(-5.08,-1.27)
  round 1.372 hole 1.016: 2(-5.08,1.27) 3(-2.54,-1.27) 4(-2.54,1.27) 5(0,-1.27) 6(0,1.27) 7(2.54,-1.27) 9(5.08,-1.27) 10(5.08,1.27)
J5X2_COM
  rect 1.372x1.372 hole 1.016: 1(-5.08,-1.27)
  round 1.372 hole 1.016: 2(-5.08,1.27) 3(-2.54,-1.27) 4(-2.54,1.27) 5(0,-1.27) 6(0,1.27) 7(2.54,-1.27) 8(2.54,1.27) 9(5.08,-1.27)
J5X2_USB_1394
  rect 1.372x1.372 hole 1.016: 1(-5.08,-1.27)
  round 1.372 hole 1.016: 2(-5.08,1.27) 3(-2.54,-1.27) 4(-2.54,1.27) 5(0,-1.27) 6(0,1.27) 7(2.54,-1.27) 8(2.54,1.27) 10(5.08,1.27)
J6X2_PT1D27MM_SMD_2P
  rect 0.711x2.54 smd: 1(-3.175,-1.75) 3(-1.905,-1.75) 4(-1.905,1.75) 5(-0.635,-1.75) 6(-0.635,1.75) 7(0.635,-1.75) 8(0.635,1.75) 9(1.905,-1.75) 10(1.905,1.75) 11(3.175,-1.75) 12(3.175,1.75)
J7X2_PANEL_10P
  rect 1.372x1.372 hole 1.016: 1(-7.62,-1.27)
  round 1.372 hole 1.016: 2(-7.62,1.27) 3(-5.08,-1.27) 4(-5.08,1.27) 5(-2.54,-1.27) 6(-2.54,1.27) 7(0,-1.27) 8(0,1.27) 9(2.54,-1.27) 11(5.08,-1.27) 12(5.08,1.27) 13(7.62,-1.27) 14(7.62,1.27)
J10X2_TPM_4P-ACER
  rect 1.372x1.372 hole 1.016: 1(-8.89,-1.27)
  round 1.372 hole 1.016: 2(-8.89,1.27) 3(-6.35,-1.27) 5(-3.81,-1.27) 6(-3.81,1.27) 7(-1.27,-1.27) 8(-1.27,1.27) 9(1.27,-1.27) 10(1.27,1.27) 11(3.81,-1.27) 12(3.81,1.27) 13(6.35,-1.27) 14(6.35,1.27) 15(8.89,-1.27) 16(8.89,1.27) 17(11.43,-1.27) 18(11.43,1.27) 19(13.97,-1.27) 20(13.97,1.27)
J13X2_LPT_1
  rect 1.372x1.372 hole 1.016: 1(-15.24,-1.27)
  round 1.372 hole 1.016: 2(-12.7,-1.27) 3(-10.16,-1.27) 4(-7.62,-1.27) 5(-5.08,-1.27) 6(-2.54,-1.27) 7(0,-1.27) 8(2.54,-1.27) 9(5.08,-1.27) 10(7.62,-1.27) 11(10.16,-1.27) 12(12.7,-1.27) 13(15.24,-1.27) 14(-15.24,1.27) 15(-12.7,1.27) 16(-10.16,1.27) 17(-7.62,1.27) 18(-5.08,1.27) 19(-2.54,1.27) 20(0,1.27) 21(2.54,1.27) 22(5.08,1.27) 23(7.62,1.27) 24(10.16,1.27) 25(12.7,1.27)
KB_MS
  rect 1.372x1.372 hole 1.016: 1(-1.397,-1.295)
  round 1.372 hole 1.016: 2(-1.397,1.295) 3(-1.397,-3.404) 4(-1.397,3.404) 5(1.092,-3.404) 6(1.092,3.404) 7(5.664,-1.295) 8(5.664,1.295) 9(5.664,-3.404) 10(5.664,3.404) 11(8.153,-3.404) 12(8.153,3.404)
  round 2.845 hole 2.489: 13(-4.394,-6.756) 14(-5.207,0) 15(-4.394,6.756) 16(5.664,6.756) 17(5.664,-6.756)
LGA1150_HSW_SKT-INTEL_1
  round 4.064 hole 4.064 unplated: (-38.12,37.5) (-38.12,-37.5) (36.89,37.5) (36.89,-37.5)
  round 3.81 hole 3.81 unplated: (-35.21,0) (25.81,18) (25.81,-18)
  round 1.016 smd: (-19.812,-19.812) (19.812,19.812)
  round 0.508 smd: A4(-16.187,18.288) AU1(-18.931,-14.63) AU39(18.016,-15.545) AU40(18.931,-15.545) AV1(-18.931,-15.545) AV2(-18.016,-15.545) AV38(17.102,-16.459) AV39(18.016,-16.459) AW2(-18.016,-16.459) AW3(-17.102,-16.459) AW37(16.187,-17.374) AW38(17.102,-17.374) AY3(-17.102,-17.374) B3(-17.102,17.374) B4(-16.187,17.374) B37(16.187,16.459) B38(17.102,16.459) B39(18.016,16.459) C2(-18.016,16.459) C3(-17.102,16.459) C39(18.016,15.545) C40(18.931,15.545) D1(-18.931,15.545) D2(-18.016,15.545) D39(18.016,14.63) D40(18.931,14.63)
  oval 0.356x0.457 smd: A5(-15.273,18.288) A6(-14.359,18.288) A7(-13.444,18.288) A11(-9.787,18.288) A12(-8.872,18.288) A13(-7.958,18.288) A14(-7.043,18.288) A15(-6.129,18.288) A16(-5.215,18.288) A17(-4.3,18.288) A18(-3.386,18.288) AU18(-1.186,-15.545) AU19(-0.272,-15.545) AU20(0.643,-15.545) AU21(1.557,-15.545) AU22(2.471,-15.545) AU23(3.386,-15.545) AV16(-3.015,-16.459) AV17(-2.101,-16.459) AV18(-1.186,-16.459) AV19(-0.272,-16.459) AV20(0.643,-16.459) AV21(1.557,-16.459) AV22(2.471,-16.459) AV23(3.386,-16.459) AV24(4.3,-16.459) AV25(5.215,-16.459) AV26(6.129,-16.459) AV27(7.043,-16.459) AV28(7.958,-16.459) AV29(8.872,-16.459) AV30(9.787,-16.459) AV31(10.701,-16.459) AV32(11.615,-16.459) AV33(12.53,-16.459) AV34(13.444,-16.459) AV35(14.359,-16.459) AV36(15.273,-16.459) AW4(-16.187,-16.459) AW5(-15.273,-16.459) AW6(-14.359,-16.459) AW7(-13.444,-16.459) AW8(-12.53,-16.459) AW9(-11.615,-16.459) AW10(-10.701,-16.459) AW11(-7.587,-17.374) AW12(-6.673,-17.374) AW13(-5.758,-17.374) AW14(-4.844,-17.374) AW15(-3.929,-17.374) AW16(-3.015,-17.374) AW17(-2.101,-17.374) AW18(-1.186,-17.374) AW23(3.386,-17.374) AW24(4.3,-17.374) AW25(5.215,-17.374) AW26(6.129,-17.374) AW27(7.043,-17.374) AW28(7.958,-17.374) AW29(8.872,-17.374) AW30(9.787,-17.374) AW31(10.701,-17.374) AW32(11.615,-17.374) AW33(12.53,-17.374) AW34(13.444,-17.374) AW35(14.359,-17.374) AW36(15.273,-17.374) AY4(-16.187,-17.374) AY5(-15.273,-17.374) AY6(-14.359,-17.374) AY7(-13.444,-17.374) AY8(-12.53,-17.374) AY9(-11.615,-17.374) AY10(-10.701,-17.374) AY11(-7.587,-18.288) AY12(-6.673,-18.288) AY13(-5.758,-18.288) AY14(-4.844,-18.288) AY15(-3.929,-18.288) AY16(-3.015,-18.288) AY17(-2.101,-18.288) AY18(-1.186,-18.288) AY23(3.386,-18.288) AY24(4.3,-18.288) AY25(5.215,-18.288) AY26(6.129,-18.288) AY27(7.043,-18.288) AY28(7.958,-18.288) AY29(8.872,-18.288) AY30(9.787,-18.288) B5(-15.273,17.374) B6(-14.359,17.374) B7(-13.444,17.374) B8(-12.53,17.374) B9(-11.615,17.374) B10(-10.701,17.374) B11(-9.787,17.374) B12(-8.872,17.374) B13(-7.958,17.374) B14(-7.043,17.374) B15(-6.129,17.374) B16(-5.215,17.374) B17(-4.3,17.374) B18(-3.386,17.374) C8(-12.53,16.459) C9(-11.615,16.459) C10(-10.701,16.459) C11(-9.787,16.459) C19(-2.471,16.459) C20(-1.557,16.459) C21(-0.643,16.459) C22(0.272,16.459) D8(-12.53,15.545) D9(-11.615,15.545) D10(-10.701,15.545) D11(-9.787,15.545) D20(-1.557,15.545) D21(-0.643,15.545)
  round 0.429 smd: A23(1.186,18.288) A24(2.101,18.288) A25(3.015,18.288) A26(3.929,18.288) A27(4.844,18.288) A28(5.758,18.288) A29(6.673,18.288) A30(7.587,18.288) AA5(-15.273,0) AA6(-14.359,0) AA7(-13.444,0) AA33(12.53,-0.914) AA34(13.444,-0.914) AA35(14.359,-0.914) AA36(15.273,-0.914) AB5(-15.273,-0.914) AB6(-14.359,-0.914) AB7(-13.444,-0.914) AB33(12.53,-1.829) AB34(13.444,-1.829) AB35(14.359,-1.829) AB36(15.273,-1.829) AB39(18.016,-1.829) AB40(18.931,-1.829) AC5(-15.273,-1.829) AC6(-14.359,-1.829) AC7(-13.444,-1.829) AC33(12.53,-2.743) AC34(13.444,-2.743) AC35(14.359,-2.743) AC36(15.273,-2.743) AC37(16.187,-2.743) AC38(17.102,-2.743) AD3(-17.102,-2.743) AD4(-16.187,-2.743) AD5(-15.273,-2.743) AD6(-14.359,-2.743) AD7(-13.444,-2.743) AD33(12.53,-3.658) AD34(13.444,-3.658) AD35(14.359,-3.658) AD36(15.273,-3.658) AD37(16.187,-3.658) AD38(17.102,-3.658) AE3(-17.102,-3.658) AE4(-16.187,-3.658) AE5(-15.273,-3.658) AE6(-14.359,-3.658) AE7(-13.444,-3.658) AE33(12.53,-4.572) AE34(13.444,-4.572) AE35(14.359,-4.572) AE36(15.273,-4.572) AE37(16.187,-4.572) AE38(17.102,-4.572) AF3(-17.102,-4.572) AF4(-16.187,-4.572) AF5(-15.273,-4.572) AF6(-14.359,-4.572) AF7(-13.444,-4.572) AF33(12.53,-5.486) AF34(13.444,-5.486) AF35(14.359,-5.486) AF36(15.273,-5.486) AF37(16.187,-5.486) AF38(17.102,-5.486) AG3(-17.102,-5.486) AG4(-16.187,-5.486) AG5(-15.273,-5.486) AG6(-14.359,-5.486) AG7(-13.444,-5.486) AG8(-12.53,-5.486) AG33(12.53,-6.401) AG34(13.444,-6.401) AG35(14.359,-6.401) AG36(15.273,-6.401) AG37(16.187,-6.401) AG38(17.102,-6.401) AH3(-17.102,-6.401) AH4(-16.187,-6.401) AH5(-15.273,-6.401) AH6(-14.359,-6.401) AH7(-13.444,-6.401) AH8(-12.53,-6.401) AH33(12.53,-7.315) AH34(13.444,-7.315) AH35(14.359,-7.315) AH36(15.273,-7.315) AH37(16.187,-7.315) AH38(17.102,-7.315) AJ3(-17.102,-7.315) AJ4(-16.187,-7.315) AJ5(-15.273,-7.315) AJ6(-14.359,-7.315) AJ7(-13.444,-7.315) AJ8(-12.53,-7.315) AJ9(-11.615,-7.315) AJ11(-7.587,-8.23) AJ12(-6.673,-8.23) AJ13(-5.758,-8.23) AJ14(-4.844,-8.23) AJ15(-3.929,-8.23) AJ16(-3.015,-8.23) AJ17(-2.101,-8.23) AJ18(-1.186,-8.23) AJ19(-0.272,-8.23) AJ20(0.643,-8.23) AJ21(1.557,-8.23) AJ22(2.471,-8.23) AJ23(3.386,-8.23) AJ24(4.3,-8.23) AJ25(5.215,-8.23) AJ26(6.129,-8.23) AJ27(7.043,-8.23) AJ28(7.958,-8.23) AJ29(8.872,-8.23) AJ30(9.787,-8.23) AJ31(10.701,-8.23) AJ32(11.615,-8.23) AJ33(12.53,-8.23) AJ34(13.444,-8.23) AJ35(14.359,-8.23) AJ36(15.273,-8.23) AJ37(16.187,-8.23) AJ38(17.102,-8.23) AK3(-17.102,-8.23) AK4(-16.187,-8.23) AK5(-15.273,-8.23) AK6(-14.359,-8.23) AK7(-13.444,-8.23) AK8(-12.53,-8.23) AK9(-11.615,-8.23) AK10(-10.701,-8.23) AK11(-7.587,-9.144) AK12(-6.673,-9.144) AK13(-5.758,-9.144) AK14(-4.844,-9.144) AK15(-3.929,-9.144) AK16(-3.015,-9.144) AK17(-2.101,-9.144) AK18(-1.186,-9.144) AK19(-0.272,-9.144) AK20(0.643,-9.144) AK21(1.557,-9.144) AK22(2.471,-9.144) AK23(3.386,-9.144) AK24(4.3,-9.144) AK25(5.215,-9.144) AK26(6.129,-9.144) AK27(7.043,-9.144) AK28(7.958,-9.144) AK29(8.872,-9.144) AK30(9.787,-9.144) AK31(10.701,-9.144) AK32(11.615,-9.144) AK33(12.53,-9.144) AK34(13.444,-9.144) AK35(14.359,-9.144) AK36(15.273,-9.144) AK37(16.187,-9.144) AK38(17.102,-9.144) AL3(-17.102,-9.144) AL4(-16.187,-9.144) AL5(-15.273,-9.144) AL6(-14.359,-9.144) AL7(-13.444,-9.144) AL8(-12.53,-9.144) AL9(-11.615,-9.144) AL10(-10.701,-9.144) AL11(-7.587,-10.058) AL12(-6.673,-10.058) AL13(-5.758,-10.058) AL14(-4.844,-10.058) AL15(-3.929,-10.058) AL16(-3.015,-10.058) AL17(-2.101,-10.058) AL18(-1.186,-10.058) AL19(-0.272,-10.058) AL20(0.643,-10.058) AL21(1.557,-10.058) AL22(2.471,-10.058) AL23(3.386,-10.058) AL24(4.3,-10.058) AL25(5.215,-10.058) AL26(6.129,-10.058) AL27(7.043,-10.058) AL28(7.958,-10.058) AL29(8.872,-10.058) AL30(9.787,-10.058) AL31(10.701,-10.058) AL32(11.615,-10.058) AL33(12.53,-10.058) AL34(13.444,-10.058) AL35(14.359,-10.058) AL36(15.273,-10.058) AL37(16.187,-10.058) AL38(17.102,-10.058) AM3(-17.102,-10.058) AM4(-16.187,-10.058) AM5(-15.273,-10.058) AM6(-14.359,-10.058) AM7(-13.444,-10.058) AM8(-12.53,-10.058) AM9(-11.615,-10.058) AM10(-10.701,-10.058) AM11(-7.587,-10.973) AM12(-6.673,-10.973) AM13(-5.758,-10.973) AM14(-4.844,-10.973) AM15(-3.929,-10.973) AM16(-3.015,-10.973) AM17(-2.101,-10.973) AM18(-1.186,-10.973) AM19(-0.272,-10.973) AM20(0.643,-10.973) AM21(1.557,-10.973) AM22(2.471,-10.973) AM23(3.386,-10.973) AM24(4.3,-10.973) AM25(5.215,-10.973) AM26(6.129,-10.973) AM27(7.043,-10.973) AM28(7.958,-10.973) AM29(8.872,-10.973) AM30(9.787,-10.973) AM31(10.701,-10.973) AM32(11.615,-10.973) AM33(12.53,-10.973) AM34(13.444,-10.973) AM35(14.359,-10.973) AM36(15.273,-10.973) AM37(16.187,-10.973) AM38(17.102,-10.973) AN3(-17.102,-10.973) AN4(-16.187,-10.973) AN5(-15.273,-10.973) AN6(-14.359,-10.973) AN7(-13.444,-10.973) AN8(-12.53,-10.973) AN9(-11.615,-10.973) AN10(-10.701,-10.973) AN11(-7.587,-11.887) AN12(-6.673,-11.887) AN13(-5.758,-11.887) AN14(-4.844,-11.887) AN15(-3.929,-11.887) AN16(-3.015,-11.887) AN17(-2.101,-11.887) AN18(-1.186,-11.887) AN19(-0.272,-11.887) AN20(0.643,-11.887) AN21(1.557,-11.887) AN22(2.471,-11.887) AN23(3.386,-11.887) AN24(4.3,-11.887) AN25(5.215,-11.887) AN26(6.129,-11.887) AN27(7.043,-11.887) AN28(7.958,-11.887) AN29(8.872,-11.887) AN30(9.787,-11.887) AN31(10.701,-11.887) AN32(11.615,-11.887) AN33(12.53,-11.887) AN34(13.444,-11.887) AN35(14.359,-11.887) AN36(15.273,-11.887) AN37(16.187,-11.887) AN38(17.102,-11.887) AP3(-17.102,-11.887) AP4(-16.187,-11.887) AP5(-15.273,-11.887) AP6(-14.359,-11.887) AP7(-13.444,-11.887) AP8(-12.53,-11.887) AP9(-11.615,-11.887) AP10(-10.701,-11.887) AP11(-7.587,-12.802) AP12(-6.673,-12.802) AP13(-5.758,-12.802) AP14(-4.844,-12.802) AP15(-3.929,-12.802) AP16(-3.015,-12.802) AP17(-2.101,-12.802) AP18(-1.186,-12.802) AP19(-0.272,-12.802) AP20(0.643,-12.802) AP21(1.557,-12.802) AP22(2.471,-12.802) AP23(3.386,-12.802) AP24(4.3,-12.802) AP25(5.215,-12.802) AP26(6.129,-12.802) AP27(7.043,-12.802) AP28(7.958,-12.802) AP29(8.872,-12.802) AP30(9.787,-12.802) AP31(10.701,-12.802) AP32(11.615,-12.802) AP33(12.53,-12.802) AP34(13.444,-12.802) AP35(14.359,-12.802) AP36(15.273,-12.802) AP37(16.187,-12.802) AP38(17.102,-12.802) AR3(-17.102,-12.802) AR4(-16.187,-12.802) AR5(-15.273,-12.802) AR6(-14.359,-12.802) AR7(-13.444,-12.802) AR8(-12.53,-12.802) AR9(-11.615,-12.802) AR10(-10.701,-12.802) AR11(-7.587,-13.716) AR12(-6.673,-13.716) AR13(-5.758,-13.716) AR14(-4.844,-13.716) AR15(-3.929,-13.716) AR16(-3.015,-13.716) AR17(-2.101,-13.716) AR18(-1.186,-13.716) AR19(-0.272,-13.716) AR20(0.643,-13.716) AR21(1.557,-13.716) AR22(2.471,-13.716) AR23(3.386,-13.716) AR24(4.3,-13.716) AR25(5.215,-13.716) AR26(6.129,-13.716) AR27(7.043,-13.716) AR28(7.958,-13.716) AR29(8.872,-13.716) AR30(9.787,-13.716) AR31(10.701,-13.716) AR32(11.615,-13.716) AR33(12.53,-13.716) AR34(13.444,-13.716) AR35(14.359,-13.716) AR36(15.273,-13.716) AR37(16.187,-13.716) AR38(17.102,-13.716) AT3(-17.102,-13.716) AT4(-16.187,-13.716) AT5(-15.273,-13.716) AT6(-14.359,-13.716) AT7(-13.444,-13.716) AT8(-12.53,-13.716) AT9(-11.615,-13.716) AT10(-10.701,-13.716) AT11(-7.587,-14.63) AT12(-6.673,-14.63) AT13(-5.758,-14.63) AT14(-4.844,-14.63) AT15(-3.929,-14.63) AT16(-3.015,-14.63) AT17(-2.101,-14.63) AT18(-1.186,-14.63) AT19(-0.272,-14.63) AT20(0.643,-14.63) AT21(1.557,-14.63) AT22(2.471,-14.63) AT23(3.386,-14.63) AT24(4.3,-14.63) AT25(5.215,-14.63) AT26(6.129,-14.63) AT27(7.043,-14.63) AT28(7.958,-14.63) AT29(8.872,-14.63) AT30(9.787,-14.63) AT31(10.701,-14.63) AT32(11.615,-14.63) AT33(12.53,-14.63) AT34(13.444,-14.63) AT35(14.359,-14.63) AT36(15.273,-14.63) AT37(16.187,-14.63) AT38(17.102,-14.63) AU3(-17.102,-14.63) AU4(-16.187,-14.63) AU5(-15.273,-14.63) AU6(-14.359,-14.63) AU7(-13.444,-14.63) AU8(-12.53,-14.63) AU9(-11.615,-14.63) AU10(-10.701,-14.63) AU11(-7.587,-15.545) AU12(-6.673,-15.545) AU13(-5.758,-15.545) AU14(-4.844,-15.545) AU15(-3.929,-15.545) AU16(-3.015,-15.545) AU17(-2.101,-15.545) AU24(4.3,-15.545) AU25(5.215,-15.545) AU26(6.129,-15.545) AU27(7.043,-15.545) AU28(7.958,-15.545) AU29(8.872,-15.545) AU30(9.787,-15.545) AU31(10.701,-15.545) AU32(11.615,-15.545) AU33(12.53,-15.545) AU34(13.444,-15.545) AU35(14.359,-15.545) AU36(15.273,-15.545) AU37(16.187,-15.545) AU38(17.102,-15.545) AV3(-17.102,-15.545) AV4(-16.187,-15.545) AV5(-15.273,-15.545) AV6(-14.359,-15.545) AV7(-13.444,-15.545) AV8(-12.53,-15.545) AV9(-11.615,-15.545) AV10(-10.701,-15.545) AV11(-7.587,-16.459) AV12(-6.673,-16.459) AV13(-5.758,-16.459) AV14(-4.844,-16.459) AV15(-3.929,-16.459) AV37(16.187,-16.459) B23(1.186,17.374) B24(2.101,17.374) B25(3.015,17.374) B26(3.929,17.374) B27(4.844,17.374) B28(5.758,17.374) B29(6.673,17.374) B30(7.587,17.374) B31(10.701,16.459) B32(11.615,16.459) B33(12.53,16.459) B34(13.444,16.459) B35(14.359,16.459) B36(15.273,16.459) C4(-16.187,16.459) C5(-15.273,16.459) C6(-14.359,16.459) C7(-13.444,16.459) C12(-8.872,16.459) C13(-7.958,16.459) C14(-7.043,16.459) C15(-6.129,16.459) C16(-5.215,16.459) C17(-4.3,16.459) C18(-3.386,16.459) C23(1.186,16.459) C24(2.101,16.459) C25(3.015,16.459) C26(3.929,16.459) C27(4.844,16.459) C28(5.758,16.459) C29(6.673,16.459) C30(7.587,16.459) C31(10.701,15.545) C32(11.615,15.545) C33(12.53,15.545) C34(13.444,15.545) C35(14.359,15.545) C36(15.273,15.545) C37(16.187,15.545) C38(17.102,15.545) D3(-17.102,15.545) D4(-16.187,15.545) D5(-15.273,15.545) D6(-14.359,15.545) D7(-13.444,15.545) D12(-8.872,15.545) D13(-7.958,15.545) D14(-7.043,15.545) D15(-6.129,15.545) D16(-5.215,15.545) D17(-4.3,15.545) D18(-3.386,15.545) D19(-2.471,15.545) D22(0.272,15.545) D23(1.186,15.545) D24(2.101,15.545) D25(3.015,15.545) D26(3.929,15.545) D27(4.844,15.545) D28(5.758,15.545) D29(6.673,15.545) D30(7.587,15.545) D31(10.701,14.63) D32(11.615,14.63) D33(12.53,14.63) D34(13.444,14.63) D35(14.359,14.63) D36(15.273,14.63) D37(16.187,14.63) D38(17.102,14.63) E4(-16.187,14.63) E5(-15.273,14.63) E6(-14.359,14.63) E7(-13.444,14.63) E8(-12.53,14.63) E9(-11.615,14.63) E10(-10.701,14.63) E11(-9.787,14.63) E12(-8.872,14.63) E13(-7.958,14.63) E14(-7.043,14.63) E15(-6.129,14.63) E16(-5.215,14.63) E17(-4.3,14.63) E18(-3.386,14.63) E19(-2.471,14.63) E20(-1.557,14.63) E21(-0.643,14.63) E22(0.272,14.63) E23(1.186,14.63) E24(2.101,14.63) E25(3.015,14.63) E26(3.929,14.63) E27(4.844,14.63) E28(5.758,14.63) E29(6.673,14.63) E30(7.587,14.63) E31(10.701,13.716) E32(11.615,13.716) E33(12.53,13.716) E34(13.444,13.716) E35(14.359,13.716) E36(15.273,13.716) E37(16.187,13.716) E38(17.102,13.716) F4(-16.187,13.716) F5(-15.273,13.716) F6(-14.359,13.716) F7(-13.444,13.716) F8(-12.53,13.716) F9(-11.615,13.716) F10(-10.701,13.716) F11(-9.787,13.716) F12(-8.872,13.716) F13(-7.958,13.716) F14(-7.043,13.716) F15(-6.129,13.716) F16(-5.215,13.716) F17(-4.3,13.716) F18(-3.386,13.716) F19(-2.471,13.716) F20(-1.557,13.716) F21(-0.643,13.716) F22(0.272,13.716) F23(1.186,13.716) F24(2.101,13.716) F25(3.015,13.716) F26(3.929,13.716) F27(4.844,13.716) F28(5.758,13.716) F29(6.673,13.716) F30(7.587,13.716) F31(10.701,12.802) F32(11.615,12.802) F33(12.53,12.802) F34(13.444,12.802) F35(14.359,12.802) F36(15.273,12.802) F37(16.187,12.802) F38(17.102,12.802) F39(18.016,12.802) G4(-16.187,12.802) G5(-15.273,12.802) G6(-14.359,12.802) G7(-13.444,12.802) G8(-12.53,12.802) G9(-11.615,12.802) G10(-10.701,12.802) G11(-9.787,12.802) G12(-8.872,12.802) G13(-7.958,12.802) G14(-7.043,12.802) G15(-6.129,12.802) G16(-5.215,12.802) G17(-4.3,12.802) G18(-3.386,12.802) G19(-2.471,12.802) G20(-1.557,12.802) G21(-0.643,12.802) G22(0.272,12.802) G23(1.186,12.802) G24(2.101,12.802) G25(3.015,12.802) G26(3.929,12.802) G27(4.844,12.802) G28(5.758,12.802) G29(6.673,12.802) G30(7.587,12.802) G31(10.701,11.887) G32(11.615,11.887) G33(12.53,11.887) G34(13.444,11.887) G35(14.359,11.887) G36(15.273,11.887) G37(16.187,11.887) G38(17.102,11.887) G39(18.016,11.887) G40(18.931,11.887) H4(-16.187,11.887) H5(-15.273,11.887) H6(-14.359,11.887) H7(-13.444,11.887) H8(-12.53,11.887) H9(-11.615,11.887) H10(-10.701,11.887) H11(-9.787,11.887) H12(-8.872,11.887) H13(-7.958,11.887) H14(-7.043,11.887) H15(-6.129,11.887) H16(-5.215,11.887) H17(-4.3,11.887) H18(-3.386,11.887) H19(-2.471,11.887) H20(-1.557,11.887) H21(-0.643,11.887) H22(0.272,11.887) H23(1.186,11.887) H24(2.101,11.887) H25(3.015,11.887) H26(3.929,11.887) H27(4.844,11.887) H28(5.758,11.887) H29(6.673,11.887) H30(7.587,11.887) H31(10.701,10.973) H32(11.615,10.973) H33(12.53,10.973) H34(13.444,10.973) H35(14.359,10.973) H36(15.273,10.973) H37(16.187,10.973) H38(17.102,10.973) H39(18.016,10.973) H40(18.931,10.973) J4(-16.187,10.973) J5(-15.273,10.973) J6(-14.359,10.973) J7(-13.444,10.973) J8(-12.53,10.973) J9(-11.615,10.973) J10(-10.701,10.973) J11(-9.787,10.973) J12(-8.872,10.973) J13(-7.958,10.973) J14(-7.043,10.973) J15(-6.129,10.973) J16(-5.215,10.973) J17(-4.3,10.973) J18(-3.386,10.973) J19(-2.471,10.973) J20(-1.557,10.973) J21(-0.643,10.973) J22(0.272,10.973) J23(1.186,10.973) J24(2.101,10.973) J25(3.015,10.973) J26(3.929,10.973) J27(4.844,10.973) J28(5.758,10.973) J29(6.673,10.973) J30(7.587,10.973) J31(10.701,10.058) J32(11.615,10.058) J33(12.53,10.058) J34(13.444,10.058) J35(14.359,10.058) J36(15.273,10.058) J37(16.187,10.058) J38(17.102,10.058) J39(18.016,10.058) J40(18.931,10.058) K4(-16.187,10.058) K5(-15.273,10.058) K6(-14.359,10.058) K7(-13.444,10.058) K8(-12.53,10.058) K9(-11.615,10.058) K10(-10.701,10.058) K11(-9.787,10.058) K12(-8.872,10.058) K13(-7.958,10.058) K14(-7.043,10.058) K15(-6.129,10.058) K16(-5.215,10.058) K17(-4.3,10.058) K18(-3.386,10.058) K19(-2.471,10.058) K20(-1.557,10.058) K21(-0.643,10.058) K22(0.272,10.058) K23(1.186,10.058) K24(2.101,10.058) K25(3.015,10.058) K26(3.929,10.058) K27(4.844,10.058) K28(5.758,10.058) K29(6.673,10.058) K30(7.587,10.058) K31(10.701,9.144) K32(11.615,9.144) K33(12.53,9.144) K34(13.444,9.144) K35(14.359,9.144) K36(15.273,9.144) K37(16.187,9.144) K38(17.102,9.144) K39(18.016,9.144) L4(-16.187,9.144) L5(-15.273,9.144) L6(-14.359,9.144) L7(-13.444,9.144) L8(-12.53,9.144) L9(-11.615,9.144) L10(-10.701,9.144) L11(-9.787,9.144) L12(-8.872,9.144) L13(-7.958,9.144) L14(-7.043,9.144) L15(-6.129,9.144) L16(-5.215,9.144) L17(-4.3,9.144) L18(-3.386,9.144) L19(-2.471,9.144) L20(-1.557,9.144) L21(-0.643,9.144) L22(0.272,9.144) L23(1.186,9.144) L24(2.101,9.144) L25(3.015,9.144) L26(3.929,9.144) L27(4.844,9.144) L28(5.758,9.144) L29(6.673,9.144) L30(7.587,9.144) L31(10.701,8.23) L32(11.615,8.23) L33(12.53,8.23) L34(13.444,8.23) L35(14.359,8.23) L36(15.273,8.23) L37(16.187,8.23) L38(17.102,8.23) L39(18.016,8.23) M4(-16.187,8.23) M5(-15.273,8.23) M6(-14.359,8.23) M7(-13.444,8.23) M8(-12.53,8.23) M9(-11.615,8.23) M10(-10.701,8.23) M11(-9.787,8.23) M12(-8.872,8.23) M13(-7.958,8.23) M14(-7.043,8.23) M15(-6.129,8.23) M16(-5.215,8.23) M17(-4.3,8.23) M18(-3.386,8.23) M19(-2.471,8.23) M20(-1.557,8.23) M21(-0.643,8.23) M22(0.272,8.23) M23(1.186,8.23) M24(2.101,8.23) M25(3.015,8.23) M26(3.929,8.23) M27(4.844,8.23) M28(5.758,8.23) M29(6.673,8.23) M30(7.587,8.23) M32(11.615,7.315) M33(12.53,7.315) M34(13.444,7.315) M35(14.359,7.315) M36(15.273,7.315) M37(16.187,7.315) M38(17.102,7.315) M39(18.016,7.315) N4(-16.187,7.315) N5(-15.273,7.315) N6(-14.359,7.315) N7(-13.444,7.315) N8(-12.53,7.315) N33(12.53,6.401) N34(13.444,6.401) N35(14.359,6.401) N36(15.273,6.401) N37(16.187,6.401) N38(17.102,6.401) N39(18.016,6.401) P4(-16.187,6.401) P5(-15.273,6.401) P6(-14.359,6.401) P7(-13.444,6.401) P8(-12.53,6.401) P33(12.53,5.486) P34(13.444,5.486) P35(14.359,5.486) P36(15.273,5.486) P37(16.187,5.486) P38(17.102,5.486) P39(18.016,5.486) R4(-16.187,5.486) R5(-15.273,5.486) R6(-14.359,5.486) R7(-13.444,5.486) R8(-12.53,5.486) R33(12.53,4.572) R34(13.444,4.572) R35(14.359,4.572) R36(15.273,4.572) R37(16.187,4.572) R38(17.102,4.572) R39(18.016,4.572) T4(-16.187,4.572) T5(-15.273,4.572) T6(-14.359,4.572) T7(-13.444,4.572) T8(-12.53,4.572) T33(12.53,3.658) T34(13.444,3.658) T35(14.359,3.658) T36(15.273,3.658) T37(16.187,3.658) T38(17.102,3.658) T39(18.016,3.658) U6(-14.359,3.658) U7(-13.444,3.658) U33(12.53,2.743) U34(13.444,2.743) U35(14.359,2.743) U36(15.273,2.743) U37(16.187,2.743) U38(17.102,2.743) V6(-14.359,2.743) V7(-13.444,2.743) V33(12.53,1.829) V34(13.444,1.829) V35(14.359,1.829) V36(15.273,1.829) V37(16.187,1.829) V38(17.102,1.829) W5(-15.273,1.829) W6(-14.359,1.829) W7(-13.444,1.829) W33(12.53,0.914) W34(13.444,0.914) W35(14.359,0.914) W36(15.273,0.914) W37(16.187,0.914) W38(17.102,0.914) Y5(-15.273,0.914) Y6(-14.359,0.914) Y7(-13.444,0.914) Y33(12.53,0) Y34(13.444,0) Y35(14.359,0) Y36(15.273,0) Y37(16.187,0)
  oval 0.457x0.356 smd: AA3(-17.102,0) AA4(-16.187,0) AA8(-12.53,0) AA37(16.187,-0.914) AA38(17.102,-0.914) AB3(-17.102,-0.914) AB4(-16.187,-0.914) AB8(-12.53,-0.914) AB37(16.187,-1.829) AB38(17.102,-1.829) AC1(-18.931,-1.829) AC2(-18.016,-1.829) AC3(-17.102,-1.829) AC4(-16.187,-1.829) AC8(-12.53,-1.829) AC39(18.016,-2.743) AC40(18.931,-2.743) AD1(-18.931,-2.743) AD2(-18.016,-2.743) AD8(-12.53,-2.743) AD39(18.016,-3.658) AD40(18.931,-3.658) AE1(-18.931,-3.658) AE2(-18.016,-3.658) AE8(-12.53,-3.658) AE39(18.016,-4.572) AE40(18.931,-4.572) AF1(-18.931,-4.572) AF2(-18.016,-4.572) AF8(-12.53,-4.572) AF39(18.016,-5.486) AF40(18.931,-5.486) AG1(-18.931,-5.486) AG2(-18.016,-5.486) AG39(18.016,-6.401) AG40(18.931,-6.401) AH1(-18.931,-6.401) AH2(-18.016,-6.401) AH39(18.016,-7.315) AH40(18.931,-7.315) AJ1(-18.931,-7.315) AJ2(-18.016,-7.315) AJ39(18.016,-8.23) AJ40(18.931,-8.23) AK1(-18.931,-8.23) AK2(-18.016,-8.23) AK39(18.016,-9.144) AK40(18.931,-9.144) AL1(-18.931,-9.144) AL2(-18.016,-9.144) AL39(18.016,-10.058) AL40(18.931,-10.058) AM1(-18.931,-10.058) AM2(-18.016,-10.058) AM39(18.016,-10.973) AM40(18.931,-10.973) AN1(-18.931,-10.973) AN2(-18.016,-10.973) AN39(18.016,-11.887) AN40(18.931,-11.887) AP1(-18.931,-11.887) AP2(-18.016,-11.887) AP39(18.016,-12.802) AP40(18.931,-12.802) AR1(-18.931,-12.802) AR2(-18.016,-12.802) AR39(18.016,-13.716) AR40(18.931,-13.716) AT1(-18.931,-13.716) AT2(-18.016,-13.716) AT39(18.016,-14.63) AT40(18.931,-14.63) AU2(-18.016,-14.63) E1(-18.931,14.63) E2(-18.016,14.63) E3(-17.102,14.63) E39(18.016,13.716) E40(18.931,13.716) F1(-18.931,13.716) F2(-18.016,13.716) F3(-17.102,13.716) F40(18.931,12.802) G1(-18.931,12.802) G2(-18.016,12.802) G3(-17.102,12.802) H1(-18.931,11.887) H2(-18.016,11.887) H3(-17.102,11.887) J1(-18.931,10.973) J2(-18.016,10.973) J3(-17.102,10.973) K1(-18.931,10.058) K2(-18.016,10.058) K3(-17.102,10.058) K40(18.931,9.144) L1(-18.931,9.144) L2(-18.016,9.144) L3(-17.102,9.144) L40(18.931,8.23) M1(-18.931,8.23) M2(-18.016,8.23) M3(-17.102,8.23) M40(18.931,7.315) N1(-18.931,7.315) N2(-18.016,7.315) N3(-17.102,7.315) N40(18.931,6.401) P1(-18.931,6.401) P2(-18.016,6.401) P3(-17.102,6.401) P40(18.931,5.486) R1(-18.931,5.486) R2(-18.016,5.486) R3(-17.102,5.486) R40(18.931,4.572) T1(-18.931,4.572) T2(-18.016,4.572) T3(-17.102,4.572) T40(18.931,3.658) U1(-18.931,3.658) U2(-18.016,3.658) U3(-17.102,3.658) U4(-16.187,3.658) U5(-15.273,3.658) U8(-12.53,3.658) U39(18.016,2.743) U40(18.931,2.743) V1(-18.931,2.743) V2(-18.016,2.743) V3(-17.102,2.743) V4(-16.187,2.743) V5(-15.273,2.743) V8(-12.53,2.743) V39(18.016,1.829) V40(18.931,1.829) W1(-18.931,1.829) W2(-18.016,1.829) W3(-17.102,1.829) W4(-16.187,1.829) W8(-12.53,1.829) Y3(-17.102,0.914) Y4(-16.187,0.914) Y8(-12.53,0.914) Y38(17.102,0)
